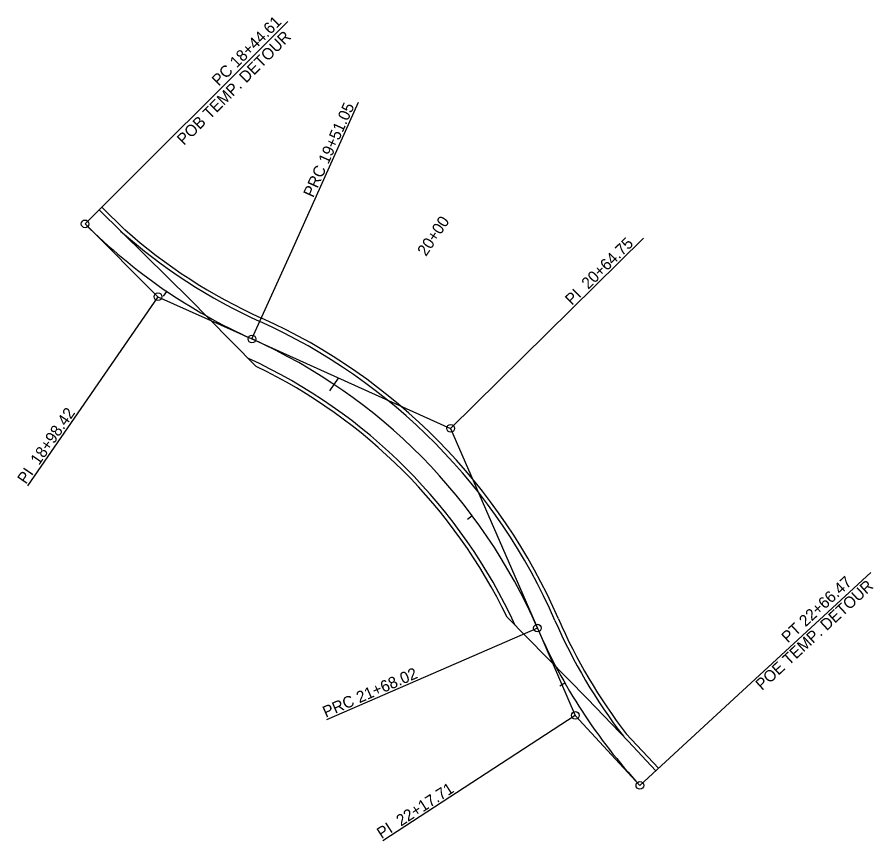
# Model space of a CAD drawing. Extents: x 1661035 to 1663788, y 668049 to 670894.
# Drawn here: x 1661096.4 to 1661543.6, y 670071.9 to 670501.9 of the extents above; entities that cross this region are included whole.
import ezdxf

# ---------------------------------------------------------------- set-up
doc = ezdxf.new("R2010")
doc.units = 0
for name, color, linetype in [('R_Annotation', 7, 'Continuous'), ('R_Horz Alg Annot', 7, 'Continuous'), ('R_Proposed Road', 7, 'Continuous'), ('R_Water', 7, 'Continuous')]:
    doc.layers.add(name, color=color, linetype=linetype)

msp = doc.modelspace()

# ---------------------------------------------------------------- linework, layer by layer
at = {"layer": 'R_Annotation'}
for centre, start, end in [((1661339.53, 670601.86), 225.0245, 245.7806), ((1661098.46, 670065.94), 23.4717, 65.7806), ((1661637.47, 670300), 203.4717, 222.6711), ((1661637.47, 670300), 203.4717, 222.6711)]:
    msp.add_arc(centre, 293.82, start, end, dxfattribs=at)
at = {"layer": 'R_Horz Alg Annot'}
for p, q in [((1661131.85, 670394.01), (1661169.92, 670355.98)), ((1661218.99, 670333.9), (1661239.73, 670380.01)), ((1661169.92, 670355.98), (1661218.99, 670333.9)), ((1661218.99, 670333.9), (1661322.68, 670287.26)), ((1661322.68, 670287.26), (1661367.97, 670182.97)), ((1661367.97, 670182.97), (1661387.76, 670137.39)), ((1661387.76, 670137.39), (1661421.44, 670100.85))]:
    msp.add_line(p, q, dxfattribs=at)
for points in [[(1661131.85, 670394.01), (1661237.71, 670499.65)], [(1661239.73, 670380.01), (1661274.6, 670457.53)], [(1661322.68, 670287.26), (1661423.32, 670386.59)], [(1661169.92, 670355.98), (1661101.78, 670257.2)], [(1661172.8, 670356.29), (1661174.48, 670358.77)], [(1661263.98, 670313.53), (1661259.53, 670306.88)], [(1661331.52, 670239.89), (1661333.93, 670241.68)], [(1661421.44, 670100.85), (1661542.08, 670212.06)], [(1661367.97, 670182.97), (1661257.89, 670135.17)], [(1661379.67, 670152.9), (1661382.27, 670154.38)], [(1661387.76, 670137.39), (1661287.2, 670071.9)]]:
    msp.add_lwpolyline(points, dxfattribs=at)
for centre in [(1661131.85, 670394.01), (1661169.92, 670355.98), (1661218.99, 670333.9), (1661322.68, 670287.26), (1661367.97, 670182.97), (1661387.76, 670137.39), (1661421.44, 670100.85)]:
    msp.add_circle(centre, 2, dxfattribs=at)
at = {"layer": 'R_Proposed Road'}
for points in [[(1661152.52, 670391.02), (1661140.62, 670402.79)], [(1661414.37, 670127.82), (1661431.25, 670109.93)]]:
    msp.add_lwpolyline(points, dxfattribs=at)
for centre, radius, start, end in [((1661339.53, 670601.86), 281.82, 228.4276, 245.7806), ((1661098.46, 670065.94), 305.82, 23.4717, 65.7806), ((1661098.46, 670065.94), 281.82, 25.8293, 64.1706), ((1661637.47, 670300), 281.82, 203.4717, 217.6583)]:
    msp.add_arc(centre, radius, start, end, dxfattribs=at)
at = {"layer": 'R_Water'}
for points in [[(1661221.24, 670319.61), (1661196.18, 670344.94), (1661186.67, 670354.44), (1661139.21, 670401.37)], [(1661352.12, 670188.73), (1661394.19, 670145.97), (1661415.33, 670123.89), (1661429.8, 670108.55)]]:
    msp.add_lwpolyline(points, dxfattribs=at)
for centre, radius, start, end in [((1661339.53, 670601.86), 283.82, 228.2052, 245.7806), ((1661098.46, 670065.94), 303.82, 23.4717, 65.7806), ((1661098.46, 670065.94), 283.82, 24.6629, 65.2815), ((1661637.47, 670300), 283.82, 203.4717, 217.6784)]:
    msp.add_arc(centre, radius, start, end, dxfattribs=at)

# ---------------------------------------------------------------- texts
at = {"layer": 'R_Horz Alg Annot'}
for s, rotation, p in [('PC 18+44.61', 45.0245, (1661201.59, 670465.62)), ('POB TEMP. DETOUR', 45.0245, (1661183.41, 670434.69)), ('PRC 19+51.05', 65.7806, (1661250.94, 670407.36)), ('PRC 19+51.05', 65.7806, (1661250.94, 670407.36)), ('20+00', 56.2352, (1661309.83, 670376.7)), ('PI  20+64.75', 44.6261, (1661385.97, 670351.13)), ('PI  18+98.42', 55.4025, (1661100.96, 670257.76)), ('PT 22+66.47', 42.6711, (1661498.73, 670174.89)), ('POE TEMP. DETOUR', 42.6711, (1661485.2, 670150.18)), ('PRC 21+68.02', 23.4717, (1661257.5, 670136.09)), ('PI  22+17.71', 33.0714, (1661286.65, 670072.74))]:
    msp.add_text(s, height=6, rotation=rotation, dxfattribs=at).set_placement(p)

doc.saveas('drawing.dxf')
